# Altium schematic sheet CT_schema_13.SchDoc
size 390 x 385 mm
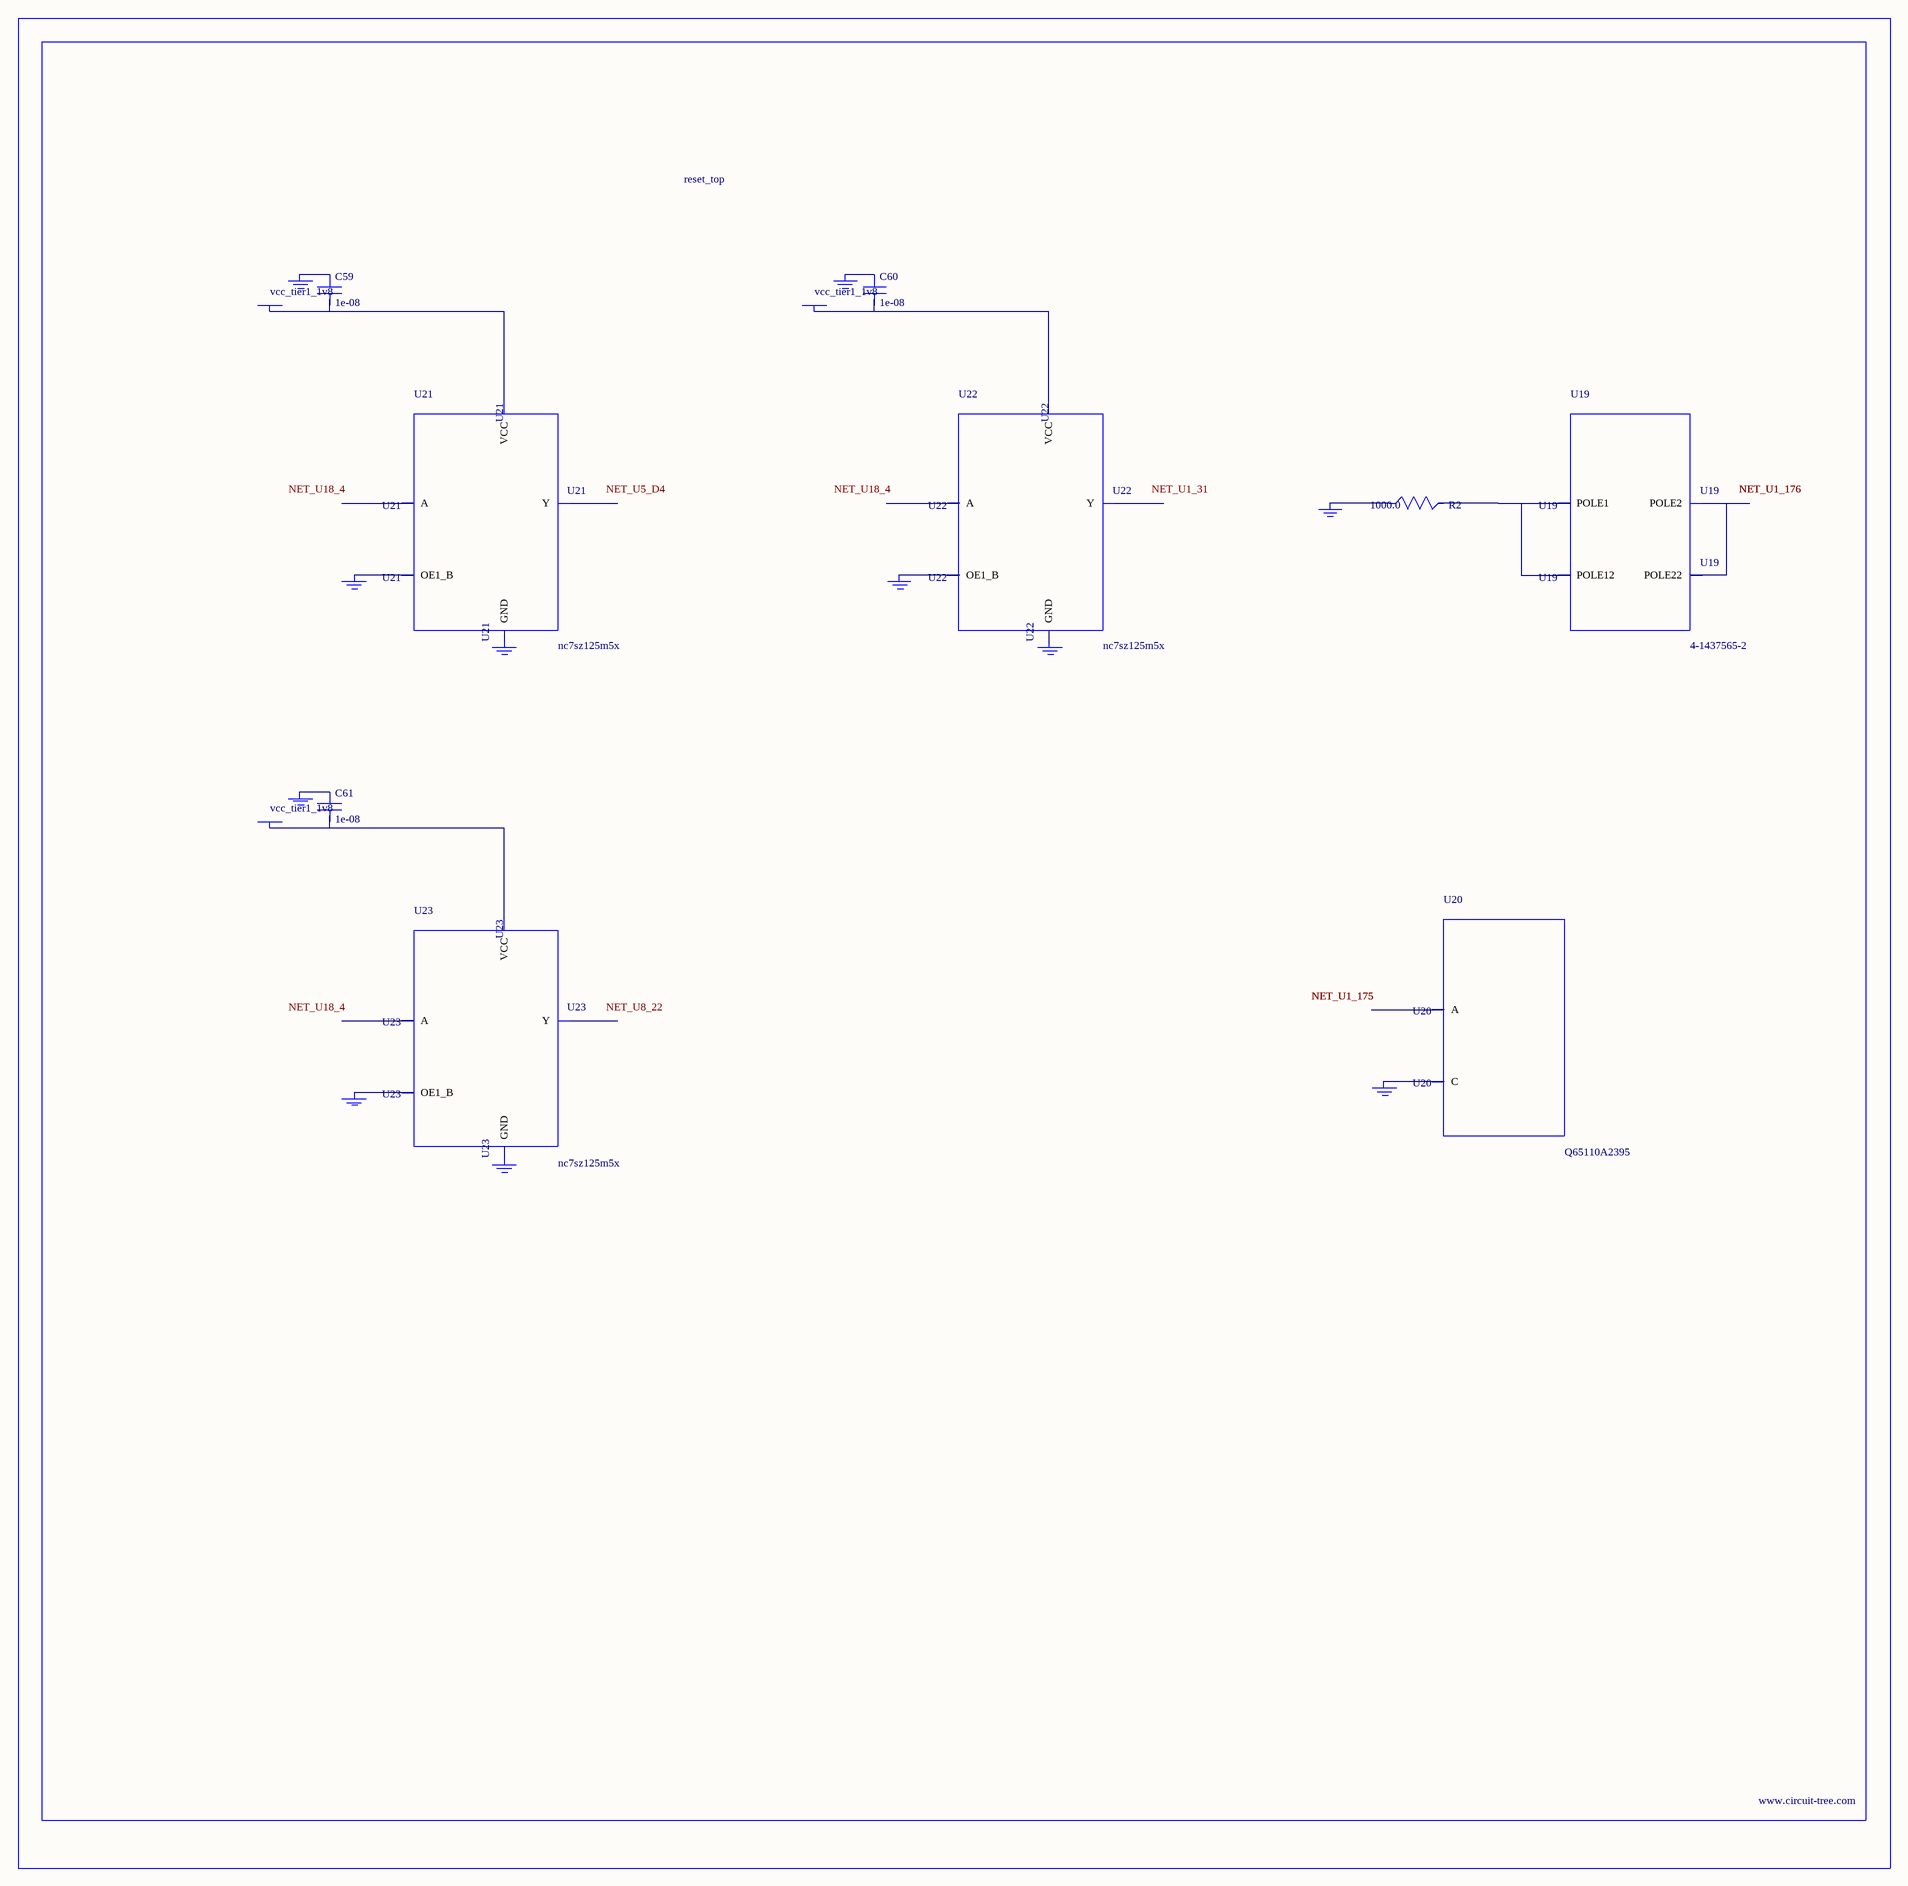
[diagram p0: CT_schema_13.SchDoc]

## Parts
BORDER12  (no value)
C59  1e-08  [C0402]
C60  1e-08  [C0402]
C61  1e-08  [C0402]
GND_INSTANCE_12_0  (no value)
GND_INSTANCE_12_1  (no value)
GND_INSTANCE_12_2  (no value)
GND_INSTANCE_12_3  (no value)
GND_INSTANCE_12_4  (no value)
GND_INSTANCE_12_5  (no value)
GND_INSTANCE_12_6  (no value)
GND_INSTANCE_12_7  (no value)
GND_INSTANCE_12_8  (no value)
GND_INSTANCE_12_9  (no value)
GND_INSTANCE_12_10  (no value)
POWER_INSTANCE_12_0  vcc_tier1_1v8
POWER_INSTANCE_12_1  vcc_tier1_1v8
POWER_INSTANCE_12_2  vcc_tier1_1v8
R2  1000.0  [R0603]
U19  4-1437565-2  [SW_4-1437565-2]
U20  Q65110A2395  [LGM67K-G1J2-24-Z]
U21  nc7sz125m5x  [NC7SZ125M5X]
U22  nc7sz125m5x  [NC7SZ125M5X]
U23  nc7sz125m5x  [NC7SZ125M5X]

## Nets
NetC59_1: C59.1 GND_INSTANCE_12_2.0(GND)
NetC59_2: C59.2 POWER_INSTANCE_12_0.0(PWR) U21.5(VCC)
NetC60_1: C60.1 GND_INSTANCE_12_5.0(GND)
NetC60_2: C60.2 POWER_INSTANCE_12_1.0(PWR) U22.5(VCC)
NetC61_1: C61.1 GND_INSTANCE_12_8.0(GND)
NetC61_2: C61.2 POWER_INSTANCE_12_2.0(PWR) U23.5(VCC)
NetGND_INSTANCE_12_0_0: GND_INSTANCE_12_0.0(GND) R2.1
NetGND_INSTANCE_12_1_0: GND_INSTANCE_12_1.0(GND) U20.C
NetGND_INSTANCE_12_3_0: GND_INSTANCE_12_3.0(GND) U21.1(OE1_B)
NetGND_INSTANCE_12_4_0: GND_INSTANCE_12_4.0(GND) U21.3(GND)
NetGND_INSTANCE_12_6_0: GND_INSTANCE_12_6.0(GND) U22.1(OE1_B)
NetGND_INSTANCE_12_7_0: GND_INSTANCE_12_7.0(GND) U22.3(GND)
NetGND_INSTANCE_12_9_0: GND_INSTANCE_12_9.0(GND) U23.1(OE1_B)
NetGND_INSTANCE_12_10_0: GND_INSTANCE_12_10.0(GND) U23.3(GND)
NetR2_2: R2.2 U19.1(POLE1) U19.2(POLE12)
NetU19_3: U19.3(POLE2) U19.4(POLE22)

Not connected (* = marked no-connect by the designer): U20 A; U21 2(A) 4(Y); U22 2(A) 4(Y); U23 2(A) 4(Y)

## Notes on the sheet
- Labels drawn without touching a wire or pin: NET_U1_31, NET_U5_D4, NET_U8_22, NET_U18_4

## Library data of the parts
BORDER12 = BORDER_PAGE12
C59-C61 = C0402C103K3RAC
GND_INSTANCE_12_0-GND_INSTANCE_12_10 = GND
POWER_INSTANCE_12_0-POWER_INSTANCE_12_2 = PWR
R2 = RC0603JR-071KL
